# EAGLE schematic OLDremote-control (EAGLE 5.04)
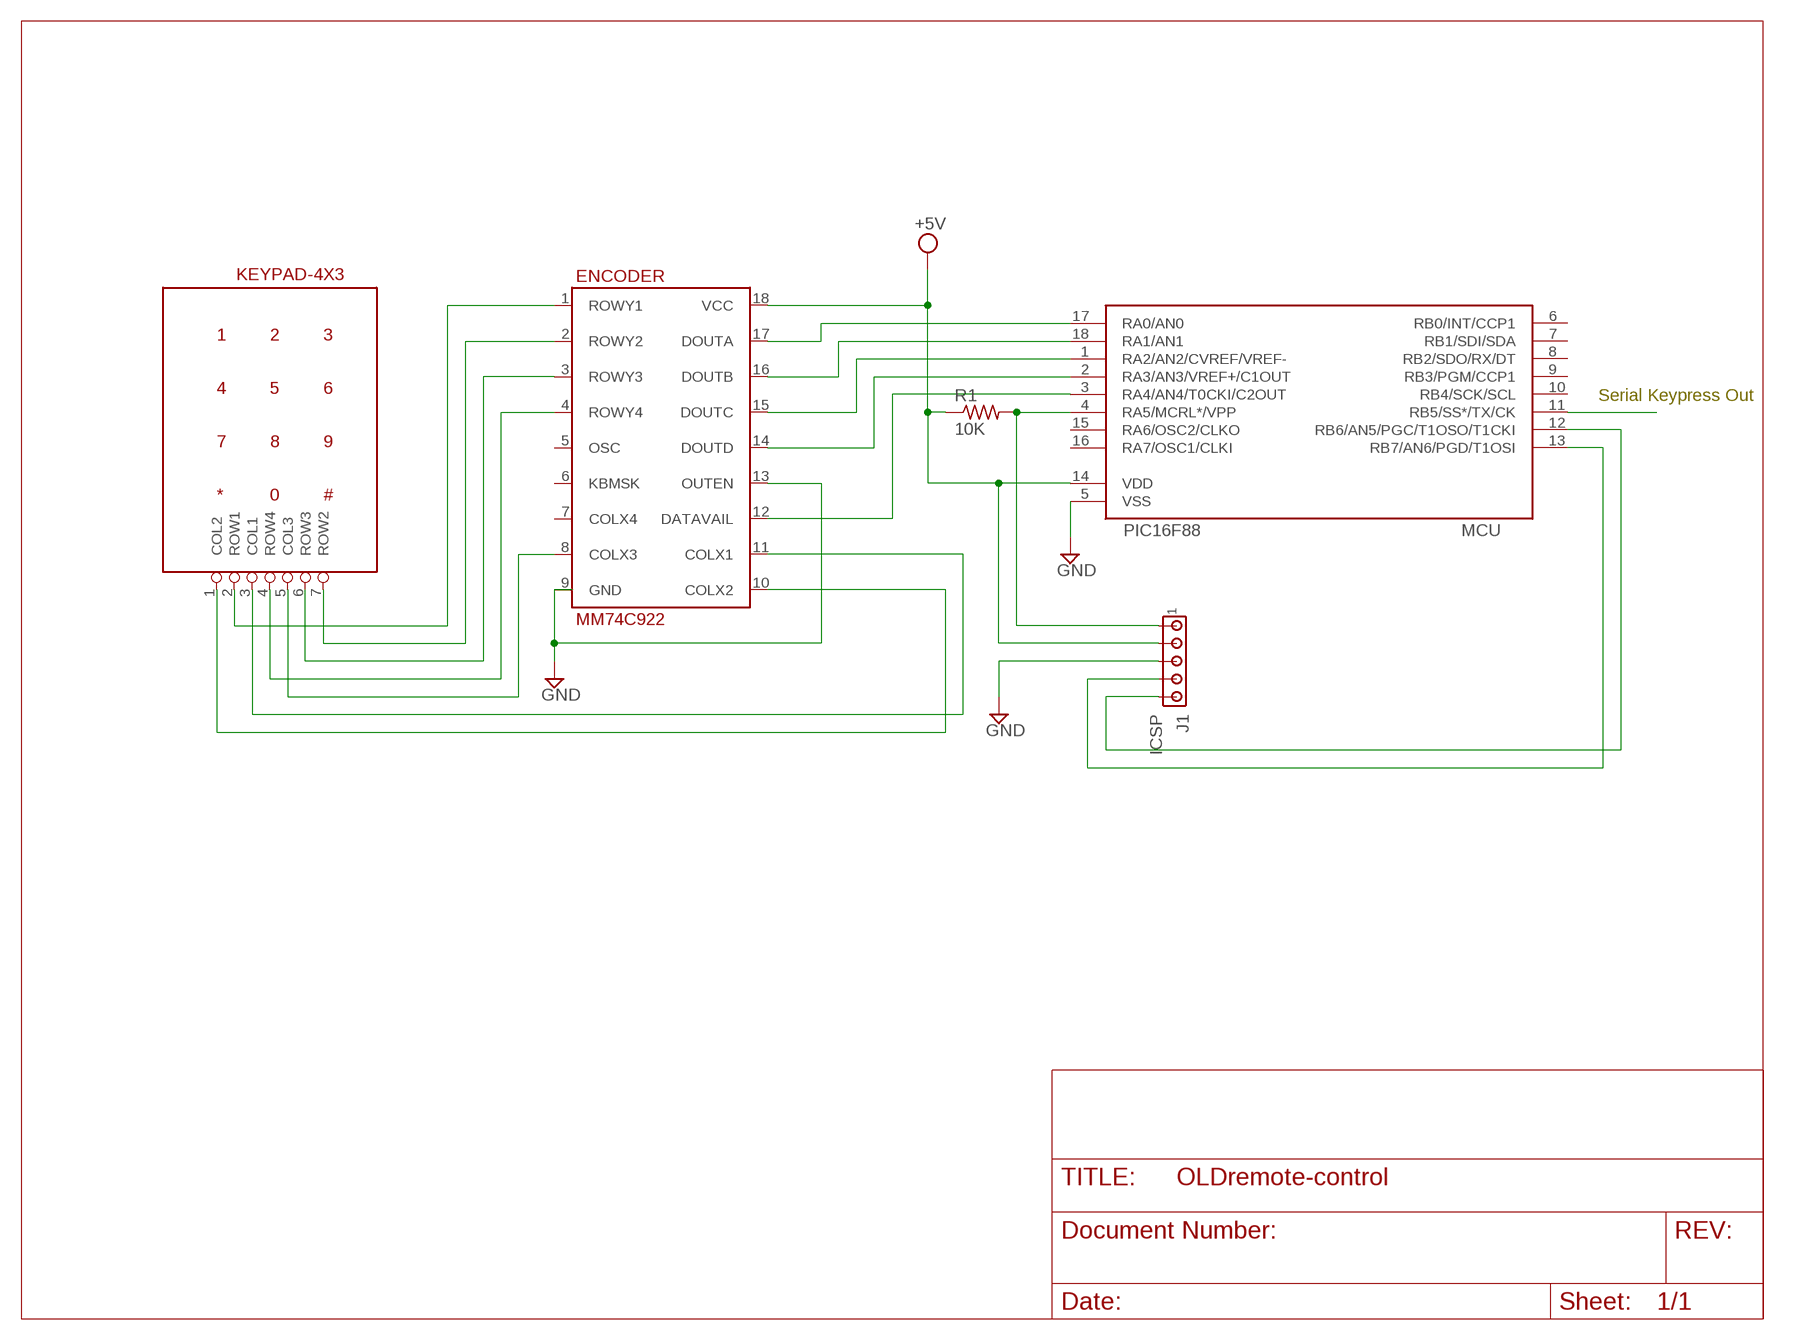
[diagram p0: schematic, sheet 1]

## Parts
ENCODER  MM74C922  [18DIL]
J1  ICSP  MTA05-100  [10X05MTA]
KEYPAD-4X3  KEYPAD43  [4X3]
MCU  PIC16F88  [DIL18]
R1  10K  R-US_0411/15  [0411/15]

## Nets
GND: ENCODER.13(OUTEN) J1.3 MCU.5(VSS)
N$1: ENCODER.10(COLX2) KEYPAD-4X3.1(COL2)
N$2: ENCODER.1(ROWY1) KEYPAD-4X3.2(ROW1)
N$3: ENCODER.11(COLX1) KEYPAD-4X3.3(COL1)
N$4: ENCODER.8(COLX3) KEYPAD-4X3.5(COL3)
N$5: ENCODER.4(ROWY4) KEYPAD-4X3.4(ROW4)
N$6: ENCODER.3(ROWY3) KEYPAD-4X3.6(ROW3)
N$7: ENCODER.2(ROWY2) KEYPAD-4X3.7(ROW2)
N$8: J1.1 MCU.4(RA5/MCRL*/VPP) R1.2
N$9: J1.5 MCU.12(RB6/AN5/PGC/T1OSO/T1CKI)
N$10: J1.4 MCU.13(RB7/AN6/PGD/T1OSI)
N$11: ENCODER.12(DATAVAIL) MCU.3(RA4/AN4/T0CKI/C2OUT)
N$12: MCU.11(RB5/SS*/TX/CK)
N$13: ENCODER.14(DOUTD) MCU.2(RA3/AN3/VREF+/C1OUT)
N$14: ENCODER.15(DOUTC) MCU.1(RA2/AN2/CVREF/VREF-)
N$15: ENCODER.16(DOUTB) MCU.18(RA1/AN1)
N$16: ENCODER.17(DOUTA) MCU.17(RA0/AN0)
VCC: ENCODER.18(VCC) J1.2 MCU.14(VDD) R1.1 ; supply symbol labelled +5V
Unconnected: ENCODER.5(OSC) ENCODER.6(KBMSK) ENCODER.7(COLX4) MCU.6(RB0/INT/CCP1) MCU.7(RB1/SDI/SDA) MCU.8(RB2/SDO/RX/DT) MCU.9(RB3/PGM/CCP1) MCU.10(RB4/SCK/SCL) MCU.15(RA6/OSC2/CLKO) MCU.16(RA7/OSC1/CLKI)

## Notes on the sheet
- Serial Keypress Out

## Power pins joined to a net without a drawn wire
GND: ENCODER.9(GND)

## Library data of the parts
ENCODER = trl:MM74C922: 16-key encoder
J1 = con-amp:MTA05-100: AMP connector
KEYPAD-4X3 = trl:KEYPAD43: 4x3 Keypad Input Device
MCU = pic16f88-v0.1:PIC16F88
R1 = resistor:R-US_: RESISTOR, American symbol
